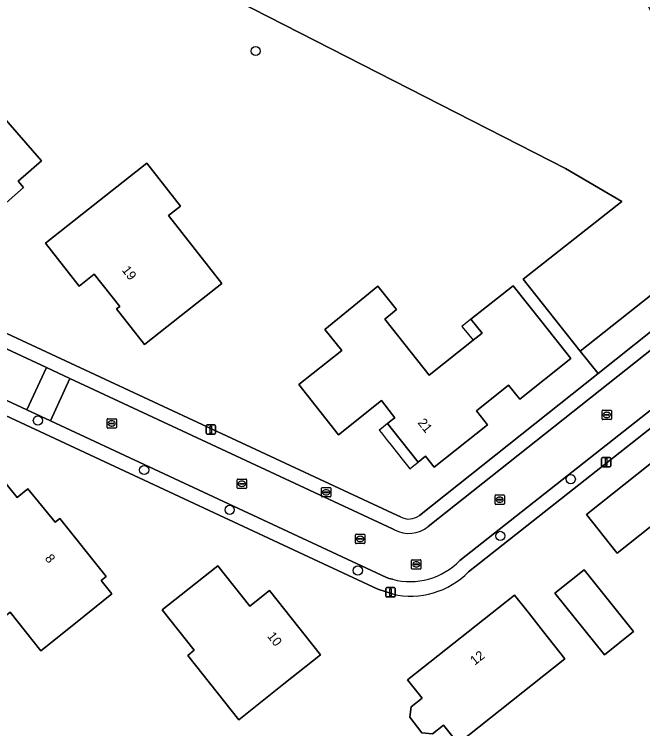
# Model space of a CAD drawing. Extents: x 159626 to 160723, y 388173 to 389416.
# Drawn here: x 159959.5 to 160026.8, y 388673.2 to 388749.5 of the extents above; entities that cross this region are included whole.
import ezdxf

# ---------------------------------------------------------------- set-up
doc = ezdxf.new("R2010")
doc.units = 0
for name, color, linetype in [('IMGEO_Boom', 7, 'Continuous'), ('IMGEO_Brandkraan', 7, 'Continuous'), ('IMGEO_Erf', 7, 'Continuous'), ('IMGEO_Groenvoorziening', 7, 'Continuous'), ('IMGEO_Kolk', 7, 'Continuous'), ('IMGEO_Lichtmast', 7, 'Continuous'), ('IMGEO_Loofbos', 7, 'Continuous'), ('IMGEO_Pand', 7, 'Continuous'), ('IMGEO_Pand_nummerreeks', 7, 'Continuous'), ('IMGEO_Pand_overbouw', 7, 'Continuous'), ('IMGEO_Rijbaan_lokaal_open', 7, 'Continuous'), ('IMGEO_Rioolput', 7, 'Continuous'), ('IMGEO_Voetpad_open', 7, 'Continuous')]:
    doc.layers.add(name, color=color, linetype=linetype)

msp = doc.modelspace()

# ---------------------------------------------------------------- linework, layer by layer
at = {"layer": 'IMGEO_Boom'}
for centre in [(159985.351, 388745.609), (159962.058, 388706.116), (159973.424, 388700.824), (160019.069, 388699.844), (159982.578, 388696.562), (160011.528, 388693.773), (159996.284, 388690.079)]:
    msp.add_circle(centre, 0.489, dxfattribs=at)
at = {"layer": 'IMGEO_Brandkraan'}
for p, q in [((159992.4, 388698.01), (159992.4, 388698.862)), ((159992.475, 388698.936), (159993.327, 388698.936)), ((159993.401, 388698.862), (159993.401, 388698.01)), ((159992.659, 388698.43), (159992.659, 388698.442)), ((159993.097, 388698.393), (159992.699, 388698.393)), ((159992.702, 388698.479), (159993.1, 388698.479)), ((159992.911, 388698.156), (159992.886, 388698.156)), ((159992.888, 388698.716), (159992.913, 388698.716)), ((159993.143, 388698.442), (159993.143, 388698.43)), ((159993.327, 388697.936), (159992.475, 388697.936))]:
    msp.add_line(p, q, dxfattribs=at)
for points in [[(159992.4, 388698.01), (159992.4, 388698.862)], [(159992.475, 388698.936), (159993.327, 388698.936)], [(159993.401, 388698.862), (159993.401, 388698.01)], [(159993.327, 388697.936), (159992.475, 388697.936)]]:
    msp.add_lwpolyline(points, dxfattribs=at)
for centre, radius, start, end in [((159992.477, 388698.86), 0.0765, 91.55205, 178.44795), ((159992.477, 388698.86), 0.0765, 91.55205, 178.44795), ((159993.325, 388698.86), 0.0765, 1.55205, 88.44795), ((159993.325, 388698.86), 0.0765, 1.55205, 88.44795), ((159992.477, 388698.012), 0.0765, 181.55205, 268.44795), ((159992.477, 388698.012), 0.0765, 181.55205, 268.44795), ((159992.699, 388698.439), 0.0403, 85.87752, 175.75265), ((159992.696, 388698.429), 0.0366, 178.93798, 274.71019), ((159993.1, 388698.436), 0.043, 264.86636, 352.45326), ((159993.104, 388698.441), 0.0386, 1.73085, 96.63898), ((159993.325, 388698.012), 0.0765, 271.55205, 358.44795), ((159993.325, 388698.012), 0.0765, 271.55205, 358.44795)]:
    msp.add_arc(centre, radius, start, end, dxfattribs=at)
for centre, major_axis, ratio, start_param, end_param in [((159992.887, 388698.436), (-0.387, 0.002), 0.722429, 4.712389, 7.853982), ((159992.912, 388698.436), (-0.39, 0.002), 0.717154, 1.570796, 4.712389)]:
    msp.add_ellipse(centre, major_axis=major_axis, ratio=ratio, start_param=start_param, end_param=end_param, dxfattribs=at)
at = {"layer": 'IMGEO_Erf'}
for points in [[(160002.873, 388695.961), (160021.986, 388711.129), (160020.086, 388713.523), (160013.968, 388721.234), (160024.53, 388729.529), (160018.506, 388733.064), (159966.614, 388759.565)], [(159937.328, 388725.355), (160000, 388696.201), (160000.854, 388695.804)], [(160000, 388687.563), (159998.439, 388688.089), (159935.176, 388717.566)], [(160034.25, 388710.535), (160008.129, 388689.947)]]:
    msp.add_lwpolyline(points, dxfattribs=at)
for points in [[(159949.905, 388728.012), (159949.287, 388728.72), (159949.665, 388729.05), (159947.029, 388732.071), (159946.652, 388731.743), (159946.034, 388732.451), (159942.929, 388736.011), (159946.305, 388738.956), (159946.233, 388739.04), (159946.898, 388739.619), (159944.123, 388742.8), (159947.605, 388745.838), (159953.932, 388738.585), (159956.433, 388740.766), (159962.451, 388733.868), (159959.958, 388731.693), (159960.536, 388731.03), (159956.772, 388727.747), (159953.004, 388724.46)], [(159962.859, 388725.061), (159966.787, 388728.155), (159973.717, 388733.615), (159977.324, 388729.036), (159976.029, 388728.017), (159981.74, 388720.768), (159977.39, 388717.341), (159973.463, 388714.247), (159970.478, 388718.035), (159970.824, 388718.307), (159968.093, 388721.774), (159966.461, 388720.488)], [(159989.984, 388709.951), (159994.588, 388713.594), (159992.753, 388715.847), (159996.63, 388719.005), (159998.414, 388720.458), (160000, 388718.511), (160000.435, 388717.977), (160000, 388717.623), (159999.178, 388716.953), (160000, 388715.916), (160003.923, 388710.968), (160008.611, 388714.685), (160009.572, 388715.447), (160008.391, 388716.935), (160012.912, 388720.52), (160015.982, 388716.649), (160019.088, 388712.731), (160013.603, 388708.377), (160012.404, 388709.889), (160008.972, 388707.157), (160010.171, 388705.645), (160004.453, 388701.116), (160003.526, 388702.292), (160002.743, 388701.67), (160000, 388705.122), (159999.472, 388705.787), (160000, 388706.206), (160000.255, 388706.409), (160000, 388706.735), (159998.828, 388708.235), (159994.225, 388704.592)], [(160020.759, 388696.061), (160032.913, 388705.71), (160035.133, 388702.915), (160036.378, 388701.349), (160037.63, 388702.344), (160041.735, 388697.175), (160037.824, 388694.061), (160034.199, 388691.176), (160029.913, 388696.589), (160024.03, 388691.93), (160023.863, 388692.141)], [(159962.37, 388681.5), (159959.084, 388685.621), (159956.68, 388683.704), (159949.069, 388693.25), (159953.987, 388697.171), (159957.867, 388700.265), (159959.834, 388697.894), (159960.981, 388698.789), (159963.891, 388695.233), (159964.389, 388695.639), (159969.359, 388689.417), (159968.845, 388689.013), (159969.977, 388687.58), (159966.072, 388684.459)], [(159983.55, 388674.11), (159978.09, 388681), (159978.794, 388681.56), (159975.37, 388685.86), (159977.4, 388687.465), (159981.322, 388690.566), (159984.721, 388686.251), (159986.848, 388687.94), (159992.295, 388681.048), (159988.379, 388677.941)], [(160017.38, 388687.639), (160020.489, 388690.139), (160025.793, 388683.546), (160022.682, 388681.045)], [(160001.857, 388674.381), (160001.994, 388675.496), (160003.17, 388676.428), (160001.615, 388678.398), (160013.059, 388687.439), (160014.643, 388685.438), (160016.163, 388683.519), (160018.447, 388680.634), (160007.017, 388671.584), (160005.466, 388673.542), (160004.275, 388672.599), (160003.151, 388672.73)]]:
    msp.add_lwpolyline(points, close=True, dxfattribs=at)
for centre, radius, start, end in [((160001.744, 388697.422), 1.846, 241.18815, 307.70473), ((160001.955, 388695.947), 8.609, 256.87377, 315.816)]:
    msp.add_arc(centre, radius, start, end, dxfattribs=at)
at = {"layer": 'IMGEO_Groenvoorziening'}
msp.add_lwpolyline([(160034.481, 388719.316), (160032.727, 388723.555), (160020.086, 388713.523), (160021.986, 388711.129), (160029.882, 388717.395)], dxfattribs=at)
at = {"layer": 'IMGEO_Kolk'}
for p, q in [((160022.412, 388706.285), (160022.412, 388707.137)), ((160022.487, 388707.211), (160023.339, 388707.211)), ((160023.413, 388707.137), (160023.413, 388706.285)), ((160022.671, 388706.705), (160022.671, 388706.717)), ((160023.109, 388706.668), (160022.711, 388706.668)), ((160022.714, 388706.754), (160023.112, 388706.754)), ((160022.923, 388706.431), (160022.898, 388706.431)), ((160022.9, 388706.991), (160022.925, 388706.991)), ((160023.155, 388706.717), (160023.155, 388706.705)), ((159969.454, 388705.374), (159969.454, 388706.226)), ((159969.529, 388706.3), (159970.381, 388706.3)), ((159969.713, 388705.794), (159969.713, 388705.806)), ((159970.151, 388705.757), (159969.753, 388705.757)), ((159969.756, 388705.843), (159970.154, 388705.843)), ((159969.942, 388706.08), (159969.967, 388706.08)), ((159970.197, 388705.806), (159970.197, 388705.794)), ((159970.455, 388706.226), (159970.455, 388705.374)), ((160023.339, 388706.211), (160022.487, 388706.211)), ((159970.381, 388705.3), (159969.529, 388705.3)), ((159969.965, 388705.52), (159969.94, 388705.52)), ((159983.38, 388698.919), (159983.38, 388699.771)), ((159983.455, 388699.845), (159984.307, 388699.845)), ((159983.868, 388699.625), (159983.893, 388699.625)), ((159984.381, 388699.771), (159984.381, 388698.919)), ((159984.307, 388698.845), (159983.455, 388698.845)), ((159983.639, 388699.339), (159983.639, 388699.351)), ((159984.077, 388699.302), (159983.679, 388699.302)), ((159983.682, 388699.388), (159984.08, 388699.388)), ((159983.891, 388699.065), (159983.866, 388699.065)), ((159984.123, 388699.351), (159984.123, 388699.339)), ((160010.964, 388697.222), (160010.964, 388698.074)), ((160011.039, 388698.148), (160011.891, 388698.148)), ((160011.965, 388698.074), (160011.965, 388697.222)), ((160011.223, 388697.642), (160011.223, 388697.654)), ((160011.661, 388697.605), (160011.263, 388697.605)), ((160011.266, 388697.691), (160011.664, 388697.691)), ((160011.475, 388697.368), (160011.45, 388697.368)), ((160011.452, 388697.928), (160011.477, 388697.928)), ((160011.707, 388697.654), (160011.707, 388697.642)), ((160011.891, 388697.148), (160011.039, 388697.148)), ((159996.032, 388693.03), (159996.032, 388693.882)), ((159996.107, 388693.956), (159996.959, 388693.956)), ((159996.291, 388693.45), (159996.291, 388693.462)), ((159996.729, 388693.413), (159996.331, 388693.413)), ((159996.334, 388693.499), (159996.732, 388693.499)), ((159996.52, 388693.736), (159996.545, 388693.736)), ((159996.775, 388693.462), (159996.775, 388693.45)), ((159997.033, 388693.882), (159997.033, 388693.03)), ((159996.959, 388692.956), (159996.107, 388692.956)), ((159996.543, 388693.176), (159996.518, 388693.176))]:
    msp.add_line(p, q, dxfattribs=at)
for points in [[(160022.412, 388706.285), (160022.412, 388707.137)], [(160022.487, 388707.211), (160023.339, 388707.211)], [(160023.413, 388707.137), (160023.413, 388706.285)], [(159969.454, 388705.374), (159969.454, 388706.226)], [(159969.529, 388706.3), (159970.381, 388706.3)], [(159970.455, 388706.226), (159970.455, 388705.374)], [(160023.339, 388706.211), (160022.487, 388706.211)], [(159970.381, 388705.3), (159969.529, 388705.3)], [(159983.38, 388698.919), (159983.38, 388699.771)], [(159983.455, 388699.845), (159984.307, 388699.845)], [(159984.381, 388699.771), (159984.381, 388698.919)], [(159984.307, 388698.845), (159983.455, 388698.845)], [(160010.964, 388697.222), (160010.964, 388698.074)], [(160011.039, 388698.148), (160011.891, 388698.148)], [(160011.965, 388698.074), (160011.965, 388697.222)], [(160011.891, 388697.148), (160011.039, 388697.148)], [(159996.032, 388693.03), (159996.032, 388693.882)], [(159996.107, 388693.956), (159996.959, 388693.956)], [(159997.033, 388693.882), (159997.033, 388693.03)], [(159996.959, 388692.956), (159996.107, 388692.956)]]:
    msp.add_lwpolyline(points, dxfattribs=at)
for centre, radius, start, end in [((160022.489, 388707.135), 0.0765, 91.55205, 178.44795), ((160022.489, 388707.135), 0.0765, 91.55205, 178.44795), ((160023.337, 388707.135), 0.0765, 1.55205, 88.44795), ((160023.337, 388707.135), 0.0765, 1.55205, 88.44795), ((160022.711, 388706.714), 0.0403, 85.87752, 175.75265), ((160022.708, 388706.704), 0.0366, 178.93798, 274.71019), ((160023.112, 388706.711), 0.043, 264.86636, 352.45326), ((160023.116, 388706.716), 0.0386, 1.73085, 96.63898), ((159969.531, 388706.224), 0.0765, 91.55205, 178.44795), ((159969.531, 388706.224), 0.0765, 91.55205, 178.44795), ((159969.753, 388705.803), 0.0403, 85.87752, 175.75265), ((159969.75, 388705.793), 0.0366, 178.93798, 274.71019), ((159970.154, 388705.8), 0.043, 264.86636, 352.45326), ((159970.158, 388705.805), 0.0386, 1.73085, 96.63898), ((159970.379, 388706.224), 0.0765, 1.55205, 88.44795), ((159970.379, 388706.224), 0.0765, 1.55205, 88.44795), ((160022.489, 388706.287), 0.0765, 181.55205, 268.44795), ((160022.489, 388706.287), 0.0765, 181.55205, 268.44795), ((160023.337, 388706.287), 0.0765, 271.55205, 358.44795), ((160023.337, 388706.287), 0.0765, 271.55205, 358.44795), ((159969.531, 388705.376), 0.0765, 181.55205, 268.44795), ((159969.531, 388705.376), 0.0765, 181.55205, 268.44795), ((159970.379, 388705.376), 0.0765, 271.55205, 358.44795), ((159970.379, 388705.376), 0.0765, 271.55205, 358.44795), ((159983.457, 388699.769), 0.0765, 91.55205, 178.44795), ((159983.457, 388699.769), 0.0765, 91.55205, 178.44795), ((159984.305, 388699.769), 0.0765, 1.55205, 88.44795), ((159984.305, 388699.769), 0.0765, 1.55205, 88.44795), ((159983.457, 388698.921), 0.0765, 181.55205, 268.44795), ((159983.457, 388698.921), 0.0765, 181.55205, 268.44795), ((159983.679, 388699.348), 0.0403, 85.87752, 175.75265), ((159983.676, 388699.338), 0.0366, 178.93798, 274.71019), ((159984.08, 388699.345), 0.043, 264.86636, 352.45326), ((159984.084, 388699.35), 0.0386, 1.73085, 96.63898), ((159984.305, 388698.921), 0.0765, 271.55205, 358.44795), ((159984.305, 388698.921), 0.0765, 271.55205, 358.44795), ((160011.041, 388698.072), 0.0765, 91.55205, 178.44795), ((160011.041, 388698.072), 0.0765, 91.55205, 178.44795), ((160011.889, 388698.072), 0.0765, 1.55205, 88.44795), ((160011.889, 388698.072), 0.0765, 1.55205, 88.44795), ((160011.041, 388697.224), 0.0765, 181.55205, 268.44795), ((160011.041, 388697.224), 0.0765, 181.55205, 268.44795), ((160011.263, 388697.651), 0.0403, 85.87752, 175.75265), ((160011.26, 388697.641), 0.0366, 178.93798, 274.71019), ((160011.664, 388697.648), 0.043, 264.86636, 352.45326), ((160011.668, 388697.653), 0.0386, 1.73085, 96.63898), ((160011.889, 388697.224), 0.0765, 271.55205, 358.44795), ((160011.889, 388697.224), 0.0765, 271.55205, 358.44795), ((159996.109, 388693.88), 0.0765, 91.55205, 178.44795), ((159996.109, 388693.88), 0.0765, 91.55205, 178.44795), ((159996.331, 388693.459), 0.0403, 85.87752, 175.75265), ((159996.328, 388693.449), 0.0366, 178.93798, 274.71019), ((159996.732, 388693.456), 0.043, 264.86636, 352.45326), ((159996.736, 388693.461), 0.0386, 1.73085, 96.63898), ((159996.957, 388693.88), 0.0765, 1.55205, 88.44795), ((159996.957, 388693.88), 0.0765, 1.55205, 88.44795), ((159996.109, 388693.032), 0.0765, 181.55205, 268.44795), ((159996.109, 388693.032), 0.0765, 181.55205, 268.44795), ((159996.957, 388693.032), 0.0765, 271.55205, 358.44795), ((159996.957, 388693.032), 0.0765, 271.55205, 358.44795)]:
    msp.add_arc(centre, radius, start, end, dxfattribs=at)
for centre, major_axis, ratio, start_param, end_param in [((160022.899, 388706.711), (-0.387, 0.002), 0.722429, 4.712389, 7.853982), ((160022.924, 388706.711), (-0.39, 0.002), 0.717154, 1.570796, 4.712389), ((159969.941, 388705.8), (-0.387, 0.002), 0.722429, 4.712389, 7.853982), ((159969.966, 388705.8), (-0.39, 0.002), 0.717154, 1.570796, 4.712389), ((159983.867, 388699.345), (-0.387, 0.002), 0.722429, 4.712389, 7.853982), ((159983.892, 388699.345), (-0.39, 0.002), 0.717154, 1.570796, 4.712389), ((160011.451, 388697.648), (-0.387, 0.002), 0.722429, 4.712389, 7.853982), ((160011.476, 388697.648), (-0.39, 0.002), 0.717154, 1.570796, 4.712389), ((159996.519, 388693.456), (-0.387, 0.002), 0.722429, 4.712389, 7.853982), ((159996.544, 388693.456), (-0.39, 0.002), 0.717154, 1.570796, 4.712389)]:
    msp.add_ellipse(centre, major_axis=major_axis, ratio=ratio, start_param=start_param, end_param=end_param, dxfattribs=at)
at = {"layer": 'IMGEO_Lichtmast'}
for p, q in [((159980.178, 388705.642), (159980.968, 388705.642)), ((159980.968, 388705.642), (159980.178, 388705.642)), ((159980.078, 388704.742), (159980.078, 388705.542)), ((159980.078, 388705.542), (159980.078, 388704.742)), ((159981.068, 388705.542), (159981.068, 388704.742)), ((159981.068, 388704.742), (159981.068, 388705.542)), ((159980.968, 388704.642), (159980.178, 388704.642)), ((159980.178, 388704.642), (159980.968, 388704.642)), ((160022.361, 388701.258), (160022.361, 388702.058)), ((160022.361, 388702.058), (160022.361, 388701.258)), ((160022.461, 388702.158), (160023.251, 388702.158)), ((160023.251, 388702.158), (160022.461, 388702.158)), ((160023.351, 388702.058), (160023.351, 388701.258)), ((160023.351, 388701.258), (160023.351, 388702.058)), ((160023.251, 388701.158), (160022.461, 388701.158)), ((160022.461, 388701.158), (160023.251, 388701.158)), ((159999.277, 388687.345), (159999.277, 388688.145)), ((159999.277, 388688.145), (159999.277, 388687.345)), ((159999.377, 388688.245), (160000.167, 388688.245)), ((160000.167, 388688.245), (159999.377, 388688.245)), ((160000.267, 388688.145), (160000.267, 388687.345)), ((160000.267, 388687.345), (160000.267, 388688.145)), ((160000.167, 388687.245), (159999.377, 388687.245)), ((159999.377, 388687.245), (160000.167, 388687.245))]:
    msp.add_line(p, q, dxfattribs=at)
for points in [[(159980.498, 388705.517), (159980.648, 388705.517), (159980.648, 388704.767), (159980.498, 388704.767), (159980.498, 388705.517)], [(160022.781, 388702.033), (160022.931, 388702.033), (160022.931, 388701.283), (160022.781, 388701.283), (160022.781, 388702.033)], [(159999.697, 388688.12), (159999.847, 388688.12), (159999.847, 388687.37), (159999.697, 388687.37), (159999.697, 388688.12)]]:
    msp.add_lwpolyline(points, dxfattribs=at)
for centre, start, end in [((159980.178, 388705.542), 90, 180), ((159980.178, 388705.542), 90, 180), ((159980.968, 388705.542), 0, 90), ((159980.968, 388705.542), 360, 90), ((159980.178, 388704.742), 180, 270), ((159980.178, 388704.742), 180, 270), ((159980.968, 388704.742), 270, 0), ((159980.968, 388704.742), 270, 0), ((160022.461, 388702.058), 90, 180), ((160022.461, 388702.058), 90, 180), ((160023.251, 388702.058), 0, 90), ((160023.251, 388702.058), 360, 90), ((160022.461, 388701.258), 180, 270), ((160022.461, 388701.258), 180, 270), ((160023.251, 388701.258), 270, 0), ((160023.251, 388701.258), 270, 0), ((159999.377, 388688.145), 90, 180), ((159999.377, 388688.145), 90, 180), ((160000.167, 388688.145), 0, 90), ((160000.167, 388688.145), 360, 90), ((159999.377, 388687.345), 180, 270), ((159999.377, 388687.345), 180, 270), ((160000.167, 388687.345), 270, 0), ((160000.167, 388687.345), 270, 0)]:
    msp.add_arc(centre, 0.1, start, end, dxfattribs=at)
at = {"layer": 'IMGEO_Loofbos'}
msp.add_lwpolyline([(159966.614, 388759.565), (160018.506, 388733.064), (160024.53, 388729.529), (160013.968, 388721.234), (160020.086, 388713.523), (160032.727, 388723.555), (160029.71, 388745.374), (160026.991, 388751.302), (160021.32, 388778.051), (160017.926, 388784.491), (160012.387, 388789.593), (160002.501, 388792.431), (159989.602, 388803.386), (159989.336, 388802.794), (159989.206, 388802.542), (159988.778, 388801.709), (159979.494, 388783.629), (159968.103, 388760.675)], dxfattribs=at)
at = {"layer": 'IMGEO_Pand'}
for points in [[(159946.034, 388732.451), (159946.652, 388731.743), (159947.029, 388732.071), (159949.665, 388729.05), (159949.287, 388728.72), (159949.905, 388728.012), (159953.004, 388724.46), (159956.772, 388727.747), (159960.536, 388731.03), (159959.958, 388731.693), (159962.451, 388733.868), (159956.433, 388740.766), (159953.932, 388738.585), (159947.605, 388745.838), (159944.123, 388742.8), (159946.898, 388739.619), (159946.233, 388739.04), (159946.305, 388738.956), (159942.929, 388736.011)], [(159966.787, 388728.155), (159962.859, 388725.061), (159966.461, 388720.488), (159968.093, 388721.774), (159970.824, 388718.307), (159970.478, 388718.035), (159973.463, 388714.247), (159977.39, 388717.341), (159981.74, 388720.768), (159976.029, 388728.017), (159977.324, 388729.036), (159973.717, 388733.615)], [(160015.982, 388716.649), (160012.912, 388720.52), (160008.391, 388716.935), (160009.572, 388715.447), (160008.611, 388714.685), (160003.923, 388710.968), (160000, 388715.916), (159999.178, 388716.953), (160000, 388717.623), (160000.435, 388717.977), (160000, 388718.511), (159998.414, 388720.458), (159996.63, 388719.005), (159992.753, 388715.847), (159994.588, 388713.594), (159989.984, 388709.951), (159994.225, 388704.592), (159998.828, 388708.235), (160000, 388706.735), (160000.255, 388706.409), (160000, 388706.206), (159999.472, 388705.787), (160000, 388705.122), (160002.743, 388701.67), (160003.526, 388702.292), (160004.453, 388701.116), (160010.171, 388705.645), (160008.972, 388707.157), (160012.404, 388709.889), (160013.603, 388708.377), (160019.088, 388712.731)], [(160035.133, 388702.915), (160032.913, 388705.71), (160020.759, 388696.061), (160023.863, 388692.141), (160024.03, 388691.93), (160029.913, 388696.589), (160034.199, 388691.176), (160037.824, 388694.061), (160041.735, 388697.175), (160037.63, 388702.344), (160036.378, 388701.349)], [(159966.072, 388684.459), (159969.977, 388687.58), (159968.845, 388689.013), (159969.359, 388689.417), (159964.389, 388695.639), (159963.891, 388695.233), (159960.981, 388698.789), (159959.834, 388697.894), (159957.867, 388700.265), (159953.987, 388697.171), (159949.069, 388693.25), (159956.68, 388683.704), (159959.084, 388685.621), (159962.37, 388681.5)], [(159988.379, 388677.941), (159992.295, 388681.048), (159986.848, 388687.94), (159984.721, 388686.251), (159981.322, 388690.566), (159977.4, 388687.465), (159975.37, 388685.86), (159978.794, 388681.56), (159978.09, 388681), (159983.55, 388674.11)], [(160017.38, 388687.639), (160022.682, 388681.045), (160025.793, 388683.546), (160020.489, 388690.139)], [(160018.447, 388680.634), (160016.163, 388683.519), (160014.643, 388685.438), (160013.059, 388687.439), (160001.615, 388678.398), (160003.17, 388676.428), (160001.994, 388675.496), (160001.857, 388674.381), (160003.151, 388672.73), (160004.275, 388672.599), (160005.466, 388673.542), (160007.017, 388671.584)]]:
    msp.add_lwpolyline(points, close=True, dxfattribs=at)
at = {"layer": 'IMGEO_Pand_overbouw'}
for points in [[(160008.391, 388716.935), (160007.765, 388716.438), (160007.428, 388716.171), (160007.627, 388715.921), (160008.611, 388714.685), (160009.572, 388715.447)], [(160002.743, 388701.67), (160000, 388705.122), (159999.472, 388705.787), (159998.822, 388705.271), (159998.571, 388705.071), (159998.802, 388704.782), (159999.474, 388703.936), (159999.704, 388703.647), (160000.668, 388702.433), (160000.898, 388702.143), (160001.607, 388701.251), (160001.842, 388700.955), (160002.093, 388701.155)]]:
    msp.add_lwpolyline(points, close=True, dxfattribs=at)
at = {"layer": 'IMGEO_Rijbaan_lokaal_open'}
for points in [[(159935.35, 388719.159), (159960.867, 388707.269), (159962.964, 388711.773), (159935.028, 388724.784), (159929.219, 388727.489), (159916.452, 388686.337), (159921.225, 388684.86), (159931.257, 388717.278)], [(160030.797, 388716.171), (160003.805, 388694.767)], [(160007.188, 388691.137), (160033.807, 388712.113)], [(159965.493, 388710.595), (159963.395, 388706.091), (159999.352, 388689.335), (159999.646, 388689.235), (160000, 388689.132)], [(160000.211, 388694.426), (160000, 388694.524), (159965.493, 388710.595)]]:
    msp.add_lwpolyline(points, dxfattribs=at)
msp.add_lwpolyline([(159965.493, 388710.595), (159962.964, 388711.773), (159960.867, 388707.269), (159963.395, 388706.091)], close=True, dxfattribs=at)
for centre, radius, start, end in [((160001.754, 388697.278), 3.242, 241.58829, 309.25175), ((160001.879, 388696.281), 7.392, 255.27041, 315.9011)]:
    msp.add_arc(centre, radius, start, end, dxfattribs=at)
at = {"layer": 'IMGEO_Rioolput'}
for p, q in [((160002.043, 388690.302), (160002.043, 388691.154)), ((160002.118, 388691.228), (160002.97, 388691.228)), ((160003.044, 388691.154), (160003.044, 388690.302)), ((160002.302, 388690.722), (160002.302, 388690.734)), ((160002.74, 388690.685), (160002.342, 388690.685)), ((160002.345, 388690.771), (160002.743, 388690.771)), ((160002.554, 388690.448), (160002.529, 388690.448)), ((160002.531, 388691.008), (160002.556, 388691.008)), ((160002.786, 388690.734), (160002.786, 388690.722)), ((160002.97, 388690.228), (160002.118, 388690.228))]:
    msp.add_line(p, q, dxfattribs=at)
for points in [[(160002.043, 388690.302), (160002.043, 388691.154)], [(160002.118, 388691.228), (160002.97, 388691.228)], [(160003.044, 388691.154), (160003.044, 388690.302)], [(160002.97, 388690.228), (160002.118, 388690.228)]]:
    msp.add_lwpolyline(points, dxfattribs=at)
for centre, radius, start, end in [((160002.12, 388691.152), 0.0765, 91.55205, 178.44795), ((160002.12, 388691.152), 0.0765, 91.55205, 178.44795), ((160002.968, 388691.152), 0.0765, 1.55205, 88.44795), ((160002.968, 388691.152), 0.0765, 1.55205, 88.44795), ((160002.342, 388690.731), 0.0403, 85.87752, 175.75265), ((160002.339, 388690.721), 0.0366, 178.93798, 274.71019), ((160002.743, 388690.728), 0.043, 264.86636, 352.45326), ((160002.747, 388690.733), 0.0386, 1.73085, 96.63898), ((160002.12, 388690.304), 0.0765, 181.55205, 268.44795), ((160002.12, 388690.304), 0.0765, 181.55205, 268.44795), ((160002.968, 388690.304), 0.0765, 271.55205, 358.44795), ((160002.968, 388690.304), 0.0765, 271.55205, 358.44795)]:
    msp.add_arc(centre, radius, start, end, dxfattribs=at)
for centre, major_axis, ratio, start_param, end_param in [((160002.53, 388690.728), (-0.387, 0.002), 0.722429, 4.712389, 7.853982), ((160002.555, 388690.728), (-0.39, 0.002), 0.717154, 1.570796, 4.712389)]:
    msp.add_ellipse(centre, major_axis=major_axis, ratio=ratio, start_param=start_param, end_param=end_param, dxfattribs=at)
at = {"layer": 'IMGEO_Voetpad_open'}
for points in [[(159936.132, 388727.911), (159935.028, 388724.784), (159962.964, 388711.773), (159965.493, 388710.595), (160000, 388694.524), (160000.211, 388694.426)], [(160000.854, 388695.804), (160000, 388696.201), (159937.328, 388725.355)], [(160000, 388689.132), (159999.646, 388689.235), (159999.352, 388689.335), (159963.395, 388706.091), (159960.867, 388707.269), (159935.35, 388719.159)], [(159935.176, 388717.566), (159998.439, 388688.089), (160000, 388687.563)], [(160029.882, 388717.395), (160021.986, 388711.129), (160002.873, 388695.961)], [(160003.805, 388694.767), (160030.797, 388716.171)], [(160033.807, 388712.113), (160007.188, 388691.137)], [(160008.129, 388689.947), (160034.25, 388710.535)]]:
    msp.add_lwpolyline(points, dxfattribs=at)
for centre, radius, start, end in [((160001.744, 388697.422), 1.846, 241.18815, 307.70473), ((160001.754, 388697.278), 3.242, 241.58829, 309.25175), ((160001.879, 388696.281), 7.392, 255.27041, 315.9011), ((160001.955, 388695.947), 8.609, 256.87377, 315.816)]:
    msp.add_arc(centre, radius, start, end, dxfattribs=at)

# ---------------------------------------------------------------- texts
at = {"layer": 'IMGEO_Pand_nummerreeks'}
for s, rotation, p in [('19', 308.22795, (159970.984, 388722.178)), ('21', 308.46751, (160002.637, 388705.855)), ('8', 308.74946, (159962.751, 388691.343)), ('10', 308.32061, (159986.543, 388683.035)), ('12', 38.30948, (160008.791, 388679.887))]:
    msp.add_text(s, height=1, rotation=rotation, dxfattribs=at).set_placement(p)

doc.saveas('drawing.dxf')
